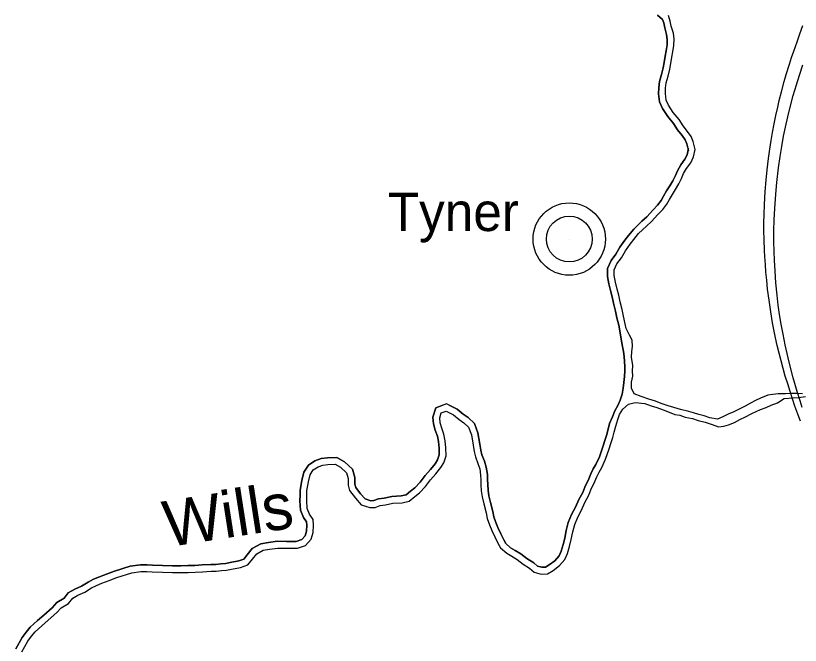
# Model space of a CAD drawing. Extents: x -29.6 to 34, y 0 to 22.
# Drawn here: x -24.65 to -23.137, y 7.479 to 8.694 of the extents above; entities that cross this region are included whole.
import ezdxf

# ---------------------------------------------------------------- set-up
doc = ezdxf.new("R2010")
doc.units = 0
for name, color, linetype in [('GM_X_Interstate_Route', 7, 'Continuous'), ('GM_X_Major_River', 7, 'Continuous'), ('GM_X_Major_River_Text', 7, 'Continuous'), ('GM_X_Unincorporated', 7, 'Continuous'), ('GM_X_Unincorporated_Location', 7, 'Continuous'), ('GM_X_Unincorporated_Text', 7, 'Continuous')]:
    doc.layers.add(name, color=color, linetype=linetype)

msp = doc.modelspace()

# ---------------------------------------------------------------- linework, layer by layer
at = {"layer": 'GM_X_Interstate_Route'}
for points in [[(-23.1365, 7.9118), (-23.1417, 7.9254), (-23.1472, 7.9407), (-23.1519, 7.9545), (-23.1566, 7.9689), (-23.1611, 7.9833), (-23.1658, 7.9983), (-23.1699, 8.0129), (-23.1741, 8.028), (-23.1778, 8.0427), (-23.1813, 8.0574), (-23.1845, 8.0722), (-23.1865, 8.0819), (-23.1902, 8.1013), (-23.1939, 8.1225), (-23.1972, 8.145), (-23.1999, 8.1664), (-23.2017, 8.1837), (-23.2031, 8.1988), (-23.2043, 8.2139), (-23.2054, 8.2295), (-23.206, 8.2412), (-23.2069, 8.2621), (-23.2072, 8.279), (-23.2071, 8.2941), (-23.2068, 8.3104), (-23.206, 8.3296), (-23.2047, 8.3546), (-23.2029, 8.3766), (-23.201, 8.3963), (-23.1983, 8.4183), (-23.1958, 8.4361), (-23.193, 8.4534), (-23.1903, 8.4683), (-23.1872, 8.4854), (-23.1839, 8.5014), (-23.1805, 8.5173), (-23.1775, 8.5304), (-23.1733, 8.5473), (-23.1682, 8.567), (-23.1643, 8.5804), (-23.1579, 8.6004), (-23.1536, 8.6131), (-23.1493, 8.6258), (-23.1432, 8.6434), (-23.1379, 8.6588), (-23.1323, 8.6747)], [(-23.133, 7.9379), (-23.1374, 7.9511), (-23.1428, 7.969), (-23.1504, 7.9953), (-23.1558, 8.015), (-23.1604, 8.0337), (-23.166, 8.0587), (-23.1702, 8.0793), (-23.1738, 8.0988), (-23.1768, 8.1172), (-23.1793, 8.1351), (-23.1815, 8.1548), (-23.1838, 8.1786), (-23.1856, 8.2012), (-23.1869, 8.2222), (-23.1875, 8.2391), (-23.1879, 8.2583), (-23.1879, 8.2793), (-23.1874, 8.3003), (-23.1863, 8.3218), (-23.1843, 8.3498), (-23.1822, 8.3724), (-23.1789, 8.4002), (-23.1759, 8.4221), (-23.1728, 8.4417), (-23.1692, 8.4612), (-23.1656, 8.4789), (-23.1611, 8.4988), (-23.1559, 8.5197), (-23.1504, 8.54), (-23.1443, 8.5607), (-23.1385, 8.579), (-23.1319, 8.5989)]]:
    msp.add_lwpolyline(points, dxfattribs=at)
at = {"layer": 'GM_X_Major_River'}
for points in [[(-23.3522, 8.4323), (-23.356, 8.447), (-23.3591, 8.4544), (-23.3648, 8.4627), (-23.3736, 8.4736), (-23.3814, 8.4862), (-23.3927, 8.4995), (-23.4027, 8.5149), (-23.4083, 8.5275), (-23.4101, 8.5432), (-23.4098, 8.5549), (-23.4086, 8.5669), (-23.4045, 8.5807), (-23.4012, 8.5936), (-23.3993, 8.6035), (-23.3976, 8.6158), (-23.3959, 8.6263), (-23.394, 8.6377), (-23.3935, 8.6482), (-23.3947, 8.6577), (-23.3985, 8.6707), (-23.4004, 8.6799), (-23.4024, 8.6867), (-23.4122, 8.6951)], [(-23.4122, 8.6951), (-23.4024, 8.6867), (-23.4004, 8.6799), (-23.3985, 8.6707), (-23.3947, 8.6577), (-23.3935, 8.6482), (-23.394, 8.6377), (-23.3959, 8.6263), (-23.3976, 8.6158), (-23.3993, 8.6035), (-23.4012, 8.5936), (-23.4045, 8.5807), (-23.4086, 8.5669), (-23.4098, 8.5549), (-23.4101, 8.5432), (-23.4083, 8.5275), (-23.4027, 8.5149), (-23.3927, 8.4995), (-23.3814, 8.4862), (-23.3736, 8.4736), (-23.3648, 8.4627), (-23.3591, 8.4544), (-23.356, 8.447), (-23.353, 8.4353)], [(-23.3396, 8.4355), (-23.3436, 8.4511), (-23.3476, 8.4607), (-23.3544, 8.4706), (-23.3629, 8.4812), (-23.3708, 8.4939), (-23.3822, 8.5073), (-23.3912, 8.5211), (-23.3955, 8.531), (-23.397, 8.5438), (-23.3967, 8.5541), (-23.3957, 8.5644), (-23.3919, 8.5772), (-23.3885, 8.5907), (-23.3864, 8.6014), (-23.3847, 8.6138), (-23.383, 8.6242), (-23.381, 8.6362), (-23.3804, 8.6487), (-23.3818, 8.6604), (-23.3858, 8.6739), (-23.3877, 8.6831), (-23.3909, 8.6941)], [(-23.353, 8.4353), (-23.3551, 8.4257), (-23.3595, 8.4171), (-23.3674, 8.4062), (-23.3737, 8.3949), (-23.3776, 8.3854), (-23.3828, 8.3756), (-23.3888, 8.3657), (-23.3949, 8.3558), (-23.4006, 8.3457), (-23.4054, 8.3375), (-23.4122, 8.3284), (-23.4209, 8.3195), (-23.4329, 8.3059), (-23.4424, 8.2977), (-23.4583, 8.2823), (-23.4685, 8.27), (-23.4754, 8.2608), (-23.485, 8.2476), (-23.4926, 8.2341), (-23.5017, 8.2219), (-23.5091, 8.2063), (-23.509, 8.191), (-23.5062, 8.1768), (-23.5028, 8.1634), (-23.4999, 8.1514), (-23.497, 8.139), (-23.4934, 8.1238), (-23.4905, 8.1111), (-23.4872, 8.0968), (-23.4844, 8.0822), (-23.4822, 8.0695), (-23.4796, 8.0555), (-23.4782, 8.0458), (-23.4767, 8.0361), (-23.4757, 8.0265), (-23.4753, 8.0168), (-23.4756, 8.0085), (-23.4762, 7.998), (-23.4775, 7.9865), (-23.4784, 7.9755), (-23.4806, 7.9634), (-23.4842, 7.9519), (-23.4889, 7.9421), (-23.4948, 7.9315), (-23.4991, 7.9197), (-23.505, 7.9073), (-23.5084, 7.8937), (-23.511, 7.8838), (-23.5141, 7.8744), (-23.5178, 7.8621), (-23.5245, 7.843), (-23.5314, 7.8279), (-23.5362, 7.8193), (-23.541, 7.8097), (-23.5449, 7.8003), (-23.5527, 7.784), (-23.5564, 7.7742), (-23.5643, 7.7605), (-23.5706, 7.7457), (-23.578, 7.7317), (-23.5846, 7.716), (-23.5883, 7.7009), (-23.5914, 7.6859), (-23.5944, 7.6733), (-23.5982, 7.661), (-23.6023, 7.6518), (-23.6107, 7.6424), (-23.6211, 7.6342), (-23.6282, 7.6299), (-23.6356, 7.6297), (-23.6439, 7.6319), (-23.6512, 7.6382), (-23.6641, 7.6466), (-23.6759, 7.6555), (-23.6869, 7.6622), (-23.6956, 7.6672), (-23.705, 7.6754), (-23.7087, 7.6823), (-23.7143, 7.6941), (-23.7203, 7.7061), (-23.7243, 7.716), (-23.7282, 7.7271), (-23.7299, 7.7371), (-23.7344, 7.7549), (-23.7375, 7.7678), (-23.7392, 7.7784), (-23.7399, 7.7892), (-23.74, 7.799), (-23.7405, 7.8088), (-23.7426, 7.8226), (-23.7463, 7.8343), (-23.7511, 7.8466), (-23.7534, 7.8558), (-23.7551, 7.867), (-23.7587, 7.889), (-23.7656, 7.9071), (-23.7777, 7.9186), (-23.7871, 7.9253), (-23.7988, 7.9347), (-23.8195, 7.9453)], [(-23.8142, 7.9426), (-23.7988, 7.9347), (-23.7871, 7.9253), (-23.7777, 7.9186), (-23.7656, 7.9071), (-23.7587, 7.889), (-23.7551, 7.867), (-23.7534, 7.8558), (-23.7511, 7.8466), (-23.7463, 7.8343), (-23.7426, 7.8226), (-23.7405, 7.8088), (-23.74, 7.799), (-23.7399, 7.7892), (-23.7392, 7.7784), (-23.7375, 7.7678), (-23.7344, 7.7549), (-23.7299, 7.7371), (-23.7282, 7.7271), (-23.7243, 7.716), (-23.7203, 7.7061), (-23.7143, 7.6941), (-23.7087, 7.6823), (-23.705, 7.6754), (-23.6956, 7.6672), (-23.6869, 7.6622), (-23.6759, 7.6555), (-23.6641, 7.6466), (-23.6512, 7.6382), (-23.6439, 7.6319), (-23.6356, 7.6297), (-23.6282, 7.6299), (-23.6211, 7.6342), (-23.6107, 7.6424), (-23.6023, 7.6518), (-23.5982, 7.661), (-23.5944, 7.6733), (-23.5914, 7.6859), (-23.5883, 7.7009), (-23.5846, 7.716), (-23.578, 7.7317), (-23.5706, 7.7457), (-23.5643, 7.7605), (-23.5564, 7.7742), (-23.5527, 7.784), (-23.5449, 7.8003), (-23.541, 7.8097), (-23.5362, 7.8193), (-23.5314, 7.8279), (-23.5245, 7.843), (-23.5178, 7.8621), (-23.5141, 7.8744), (-23.511, 7.8838), (-23.5084, 7.8937), (-23.505, 7.9073), (-23.4991, 7.9197), (-23.4948, 7.9315), (-23.4889, 7.9421), (-23.4842, 7.9519), (-23.4806, 7.9634), (-23.4784, 7.9755), (-23.4775, 7.9865), (-23.4762, 7.998), (-23.4756, 8.0085), (-23.4753, 8.0168), (-23.4757, 8.0265), (-23.4767, 8.0361), (-23.4782, 8.0458), (-23.4796, 8.0555), (-23.4822, 8.0695), (-23.4844, 8.0822), (-23.4872, 8.0968), (-23.4905, 8.1111), (-23.4934, 8.1238), (-23.497, 8.139), (-23.4999, 8.1514), (-23.5028, 8.1634), (-23.5062, 8.1768), (-23.509, 8.191), (-23.5091, 8.2063), (-23.5017, 8.2219), (-23.4926, 8.2341), (-23.485, 8.2476), (-23.4754, 8.2608), (-23.4685, 8.27), (-23.4583, 8.2823), (-23.4424, 8.2977), (-23.4329, 8.3059), (-23.4209, 8.3195), (-23.4122, 8.3284), (-23.4054, 8.3375), (-23.4006, 8.3457), (-23.3949, 8.3558), (-23.3888, 8.3657), (-23.3828, 8.3756), (-23.3776, 8.3854), (-23.3737, 8.3949), (-23.3674, 8.4062), (-23.3595, 8.4171), (-23.3551, 8.4257), (-23.3524, 8.4383)], [(-23.4726, 8.0902), (-23.4745, 8.0995), (-23.4777, 8.114), (-23.4807, 8.1268), (-23.4843, 8.142), (-23.4872, 8.1545), (-23.4901, 8.1665), (-23.4934, 8.1796), (-23.496, 8.1924), (-23.4961, 8.2034), (-23.4905, 8.2152), (-23.4817, 8.227), (-23.474, 8.2405), (-23.4649, 8.253), (-23.4582, 8.262), (-23.4487, 8.2734), (-23.4336, 8.2881), (-23.4237, 8.2967), (-23.4114, 8.3106), (-23.4022, 8.3199), (-23.3945, 8.3303), (-23.3893, 8.3392), (-23.3837, 8.3492), (-23.3777, 8.3588), (-23.3714, 8.3692), (-23.3658, 8.3799), (-23.362, 8.3892), (-23.3564, 8.3991), (-23.3483, 8.4102), (-23.3427, 8.4213), (-23.3396, 8.4355)], [(-23.3919, 7.9413), (-23.405, 7.9455), (-23.4164, 7.95), (-23.4288, 7.9542), (-23.4438, 7.959), (-23.4573, 7.9646), (-23.4626, 7.9752), (-23.4624, 7.9866), (-23.46, 7.9984), (-23.4604, 8.0079), (-23.4601, 8.0193), (-23.4623, 8.0353), (-23.4617, 8.0463), (-23.4603, 8.0555), (-23.4611, 8.0676), (-23.4662, 8.0772), (-23.4726, 8.0902)], [(-23.1324, 7.9646), (-23.1419, 7.9649), (-23.1561, 7.9648), (-23.1653, 7.9644), (-23.1798, 7.9643), (-23.1901, 7.9628), (-23.1997, 7.962), (-23.2134, 7.9558), (-23.223, 7.9515), (-23.2329, 7.9465), (-23.2435, 7.9403), (-23.2533, 7.9356), (-23.2653, 7.9295), (-23.2759, 7.9248), (-23.2862, 7.9198), (-23.2964, 7.9154), (-23.3113, 7.9178), (-23.3223, 7.922), (-23.3326, 7.9247), (-23.3426, 7.9279), (-23.3518, 7.9303), (-23.3678, 7.9341), (-23.3809, 7.9379), (-23.3919, 7.9413)], [(-23.1324, 7.9646), (-23.1419, 7.9649), (-23.1561, 7.9648), (-23.1653, 7.9644), (-23.1798, 7.9643), (-23.1901, 7.9628), (-23.1997, 7.962), (-23.2134, 7.9558), (-23.223, 7.9515), (-23.2329, 7.9465), (-23.2435, 7.9403), (-23.2533, 7.9356), (-23.2653, 7.9295), (-23.2759, 7.9248), (-23.2862, 7.9198), (-23.2964, 7.9154), (-23.3113, 7.9178), (-23.3223, 7.922), (-23.3326, 7.9247), (-23.3426, 7.9279), (-23.3518, 7.9303), (-23.3678, 7.9341), (-23.3809, 7.9379), (-23.3919, 7.9413)], [(-23.4928, 7.9021), (-23.4888, 7.915), (-23.4857, 7.9246), (-23.4794, 7.935), (-23.4685, 7.9447), (-23.4554, 7.9476), (-23.4369, 7.9456), (-23.4245, 7.9411), (-23.4139, 7.938), (-23.4014, 7.9334), (-23.3901, 7.9289), (-23.3787, 7.9247), (-23.3695, 7.923), (-23.3588, 7.9192), (-23.3446, 7.9168), (-23.334, 7.913), (-23.3205, 7.9099), (-23.307, 7.9054), (-23.2946, 7.9009), (-23.2846, 7.9017), (-23.2751, 7.9046), (-23.2641, 7.9093), (-23.2536, 7.9147), (-23.2426, 7.9201), (-23.2306, 7.9262), (-23.2136, 7.9338), (-23.2027, 7.9382), (-23.1928, 7.9425), (-23.1808, 7.9472), (-23.1677, 7.9555), (-23.1504, 7.9567), (-23.1405, 7.9571), (-23.127, 7.9594)], [(-23.4928, 7.9021), (-23.4888, 7.915), (-23.4857, 7.9246), (-23.4794, 7.935), (-23.4685, 7.9447), (-23.4554, 7.9476), (-23.4369, 7.9456), (-23.4245, 7.9411), (-23.4139, 7.938), (-23.4014, 7.9334), (-23.3901, 7.9289), (-23.3787, 7.9247), (-23.3695, 7.923), (-23.3588, 7.9192), (-23.3446, 7.9168), (-23.334, 7.913), (-23.3205, 7.9099), (-23.307, 7.9054), (-23.2946, 7.9009), (-23.2846, 7.9017), (-23.2751, 7.9046), (-23.2641, 7.9093), (-23.2536, 7.9147), (-23.2426, 7.9201), (-23.2306, 7.9262), (-23.2136, 7.9338), (-23.2027, 7.9382), (-23.1928, 7.9425), (-23.1808, 7.9472), (-23.1677, 7.9555), (-23.1504, 7.9567), (-23.1405, 7.9571), (-23.127, 7.9594)], [(-23.8195, 7.9453), (-23.8402, 7.9372), (-23.8454, 7.9191), (-23.8443, 7.9062), (-23.8409, 7.8943), (-23.8368, 7.8828), (-23.8349, 7.8721), (-23.8338, 7.8594), (-23.8332, 7.8466), (-23.8367, 7.8368), (-23.8412, 7.8294), (-23.85, 7.8184), (-23.8602, 7.8066), (-23.87, 7.7942), (-23.8802, 7.7828), (-23.8886, 7.7763), (-23.8971, 7.7692), (-23.9068, 7.7672), (-23.9245, 7.7663), (-23.9393, 7.7633), (-23.9505, 7.7616), (-23.9597, 7.7582), (-23.9652, 7.758), (-23.9764, 7.7617), (-23.9851, 7.7711), (-23.9943, 7.7835), (-23.9961, 7.7897), (-23.9962, 7.8028), (-24.0005, 7.819), (-24.0158, 7.8332), (-24.031, 7.8417), (-24.049, 7.8411), (-24.0612, 7.8397), (-24.0731, 7.8351), (-24.0858, 7.827), (-24.0944, 7.8131), (-24.0985, 7.7971), (-24.1015, 7.7782), (-24.1018, 7.7685), (-24.1021, 7.7579), (-24.1007, 7.74), (-24.0952, 7.7259), (-24.0894, 7.7171), (-24.0887, 7.7108), (-24.0895, 7.6992), (-24.0921, 7.6905), (-24.0987, 7.6832), (-24.1092, 7.6797), (-24.1169, 7.6794), (-24.1282, 7.6797), (-24.1452, 7.6799), (-24.1627, 7.6775), (-24.1774, 7.6749), (-24.194, 7.6661), (-24.2038, 7.6535), (-24.2102, 7.6453), (-24.2202, 7.642), (-24.2365, 7.6386), (-24.2452, 7.6372), (-24.2549, 7.6364), (-24.2645, 7.6353), (-24.2737, 7.6349), (-24.2904, 7.6341), (-24.3048, 7.6333), (-24.3181, 7.6328), (-24.3316, 7.6324), (-24.3479, 7.6326), (-24.3669, 7.6332), (-24.3866, 7.6337), (-24.3967, 7.6344), (-24.4097, 7.6343), (-24.4293, 7.6318), (-24.4598, 7.6222), (-24.4751, 7.6163), (-24.4888, 7.6109), (-24.5002, 7.6066), (-24.5103, 7.601), (-24.5234, 7.5933), (-24.5363, 7.5873), (-24.5489, 7.5804), (-24.557, 7.5699), (-24.5712, 7.5618), (-24.5802, 7.5515), (-24.5964, 7.5371), (-24.6084, 7.5267), (-24.6223, 7.5144), (-24.6301, 7.5045), (-24.6381, 7.4941), (-24.6504, 7.4725)], [(-24.6504, 7.4725), (-24.6381, 7.4941), (-24.6301, 7.5045), (-24.6223, 7.5144), (-24.6084, 7.5267), (-24.5964, 7.5371), (-24.5802, 7.5515), (-24.5712, 7.5618), (-24.557, 7.5699), (-24.5489, 7.5804), (-24.5363, 7.5873), (-24.5234, 7.5933), (-24.5103, 7.601), (-24.5002, 7.6066), (-24.4888, 7.6109), (-24.4751, 7.6163), (-24.4598, 7.6222), (-24.4293, 7.6318), (-24.4097, 7.6343), (-24.3967, 7.6344), (-24.3866, 7.6337), (-24.3669, 7.6332), (-24.3479, 7.6326), (-24.3316, 7.6324), (-24.3181, 7.6328), (-24.3048, 7.6333), (-24.2904, 7.6341), (-24.2737, 7.6349), (-24.2645, 7.6353), (-24.2549, 7.6364), (-24.2452, 7.6372), (-24.2365, 7.6386), (-24.2202, 7.642), (-24.2102, 7.6453), (-24.2038, 7.6535), (-24.194, 7.6661), (-24.1774, 7.6749), (-24.1627, 7.6775), (-24.1452, 7.6799), (-24.1282, 7.6797), (-24.1169, 7.6794), (-24.1092, 7.6797), (-24.0987, 7.6832), (-24.0921, 7.6905), (-24.0895, 7.6992), (-24.0887, 7.7108), (-24.0894, 7.7171), (-24.0952, 7.7259), (-24.1007, 7.74), (-24.1021, 7.7579), (-24.1018, 7.7685), (-24.1015, 7.7782), (-24.0985, 7.7971), (-24.0944, 7.8131), (-24.0858, 7.827), (-24.0731, 7.8351), (-24.0612, 7.8397), (-24.049, 7.8411), (-24.031, 7.8417), (-24.0158, 7.8332), (-24.0005, 7.819), (-23.9962, 7.8028), (-23.9961, 7.7897), (-23.9943, 7.7835), (-23.9851, 7.7711), (-23.9764, 7.7617), (-23.9652, 7.758), (-23.9597, 7.7582), (-23.9505, 7.7616), (-23.9393, 7.7633), (-23.9245, 7.7663), (-23.9068, 7.7672), (-23.8971, 7.7692), (-23.8886, 7.7763), (-23.8802, 7.7828), (-23.87, 7.7942), (-23.8602, 7.8066), (-23.85, 7.8184), (-23.8412, 7.8294), (-23.8367, 7.8368), (-23.8332, 7.8466), (-23.8338, 7.8594), (-23.8349, 7.8721), (-23.8368, 7.8828), (-23.8409, 7.8943), (-23.8443, 7.9062), (-23.8454, 7.9191), (-23.8402, 7.9372), (-23.825, 7.9432)], [(-24.6388, 7.4665), (-24.6272, 7.4868), (-24.6198, 7.4965), (-24.6128, 7.5054), (-24.5998, 7.5169), (-24.5878, 7.5273), (-24.5709, 7.5423), (-24.5628, 7.5516), (-24.5483, 7.5599), (-24.5402, 7.5702), (-24.5304, 7.5756), (-24.5173, 7.5818), (-24.5039, 7.5897), (-24.4947, 7.5947), (-24.4841, 7.5987), (-24.4703, 7.6041), (-24.4555, 7.6099), (-24.4265, 7.619), (-24.4088, 7.6213), (-24.3971, 7.6213), (-24.3872, 7.6207), (-24.3673, 7.6201), (-24.3482, 7.6196), (-24.3315, 7.6193), (-24.3177, 7.6198), (-24.3042, 7.6202), (-24.2897, 7.621), (-24.2731, 7.6219), (-24.2635, 7.6223), (-24.2536, 7.6234), (-24.2437, 7.6242), (-24.2341, 7.6257), (-24.2168, 7.6294), (-24.2023, 7.6341), (-24.1935, 7.6455), (-24.1854, 7.6559), (-24.1731, 7.6624), (-24.1607, 7.6646), (-24.1444, 7.6668), (-24.1285, 7.6666), (-24.1168, 7.6663), (-24.1068, 7.6668), (-24.0913, 7.6718), (-24.0804, 7.684), (-24.0766, 7.6968), (-24.0756, 7.711), (-24.0767, 7.7217), (-24.0835, 7.7319), (-24.0879, 7.7429), (-24.089, 7.7582), (-24.0887, 7.7681), (-24.0885, 7.777), (-24.0857, 7.7944), (-24.0823, 7.808), (-24.0763, 7.8176), (-24.0671, 7.8234), (-24.058, 7.827), (-24.048, 7.8281), (-24.0342, 7.8286), (-24.0236, 7.8226), (-24.0122, 7.812), (-24.0092, 7.801), (-24.0092, 7.7879), (-24.0063, 7.7776), (-23.9952, 7.7628), (-23.9837, 7.7504), (-23.9671, 7.7449), (-23.9571, 7.7453), (-23.9472, 7.7489), (-23.937, 7.7504), (-23.9228, 7.7534), (-23.9051, 7.7542), (-23.8913, 7.7571), (-23.8804, 7.7661), (-23.8712, 7.7733), (-23.86, 7.7858), (-23.8501, 7.7983), (-23.8399, 7.8101), (-23.8305, 7.8219), (-23.8248, 7.8312), (-23.82, 7.8447), (-23.8208, 7.8603), (-23.8219, 7.8738), (-23.8242, 7.8862), (-23.8285, 7.8983), (-23.8314, 7.9085), (-23.8322, 7.9178), (-23.8294, 7.9274), (-23.8202, 7.931)], [(-23.8202, 7.931), (-23.806, 7.9237), (-23.7949, 7.9149), (-23.786, 7.9085), (-23.7768, 7.8997), (-23.7714, 7.8855), (-23.768, 7.865), (-23.7662, 7.8533), (-23.7636, 7.8426), (-23.7586, 7.8299), (-23.7553, 7.8196), (-23.7535, 7.8075), (-23.7531, 7.7986), (-23.753, 7.7887), (-23.7522, 7.777), (-23.7504, 7.7653), (-23.7471, 7.7518), (-23.7427, 7.7344), (-23.7409, 7.7238), (-23.7365, 7.7114), (-23.7322, 7.7008), (-23.7261, 7.6884), (-23.7203, 7.6763), (-23.7153, 7.6671), (-23.7032, 7.6566), (-23.6936, 7.651), (-23.6833, 7.6446), (-23.6715, 7.6358), (-23.6591, 7.6278), (-23.6502, 7.62), (-23.637, 7.6166), (-23.6243, 7.617), (-23.6137, 7.6235), (-23.6017, 7.6328), (-23.5912, 7.6446), (-23.5859, 7.6564), (-23.5818, 7.6699), (-23.5787, 7.6831), (-23.5756, 7.698), (-23.5721, 7.7119), (-23.5662, 7.7262), (-23.5589, 7.7401), (-23.5526, 7.7547), (-23.5445, 7.7686), (-23.5407, 7.7789), (-23.533, 7.795), (-23.5292, 7.8042), (-23.5246, 7.8131), (-23.5197, 7.8221), (-23.5124, 7.8381), (-23.5054, 7.8581), (-23.5016, 7.8705), (-23.4985, 7.8801), (-23.4957, 7.8904), (-23.4928, 7.9021)]]:
    msp.add_lwpolyline(points, dxfattribs=at)
at = {"layer": 'GM_X_Unincorporated'}
for radius in [0.0698, 0.0442]:
    msp.add_circle((-23.5825, 8.263), radius, dxfattribs=at)
at = {"layer": 'GM_X_Unincorporated_Location'}
msp.add_line((-23.5825, 8.263), (-23.5825, 8.263), dxfattribs=at)

# ---------------------------------------------------------------- texts
at = {"layer": 'GM_X_Major_River_Text'}
msp.add_text('Wills', height=0.08878, rotation=8.8402, dxfattribs=at).set_placement((-24.358, 7.6682))
at = {"layer": 'GM_X_Unincorporated_Text'}
msp.add_text('Tyner', height=0.07404, rotation=0, dxfattribs=at).set_placement((-23.9327, 8.2784))

doc.saveas('drawing.dxf')
